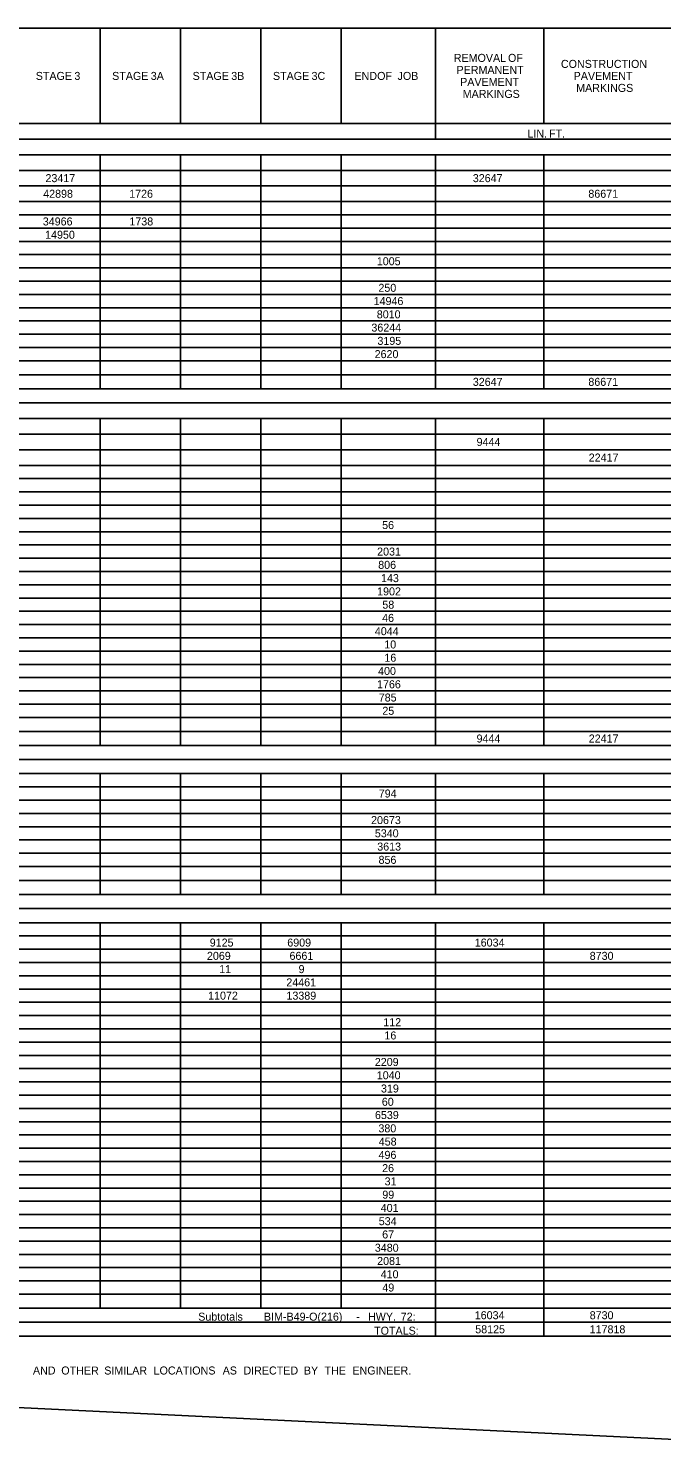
# Model space of a CAD drawing. Extents: x 1225909 to 1228704, y 151309 to 152305.
# Drawn here: x 1226949 to 1227206, y 151342 to 151915 of the extents above; entities that cross this region are included whole.
import ezdxf

# ---------------------------------------------------------------- set-up
doc = ezdxf.new("R2010")
doc.units = 0
doc.layers.add('R_Border', color=7, linetype='Continuous')
doc.layers.add('R_Dimension', color=7, linetype='Continuous')

msp = doc.modelspace()

# ---------------------------------------------------------------- linework, layer by layer
at = {"layer": 'R_Border'}
msp.add_lwpolyline([(1227672.06, 151397.84), (1227247.19, 151342), (1225968.58, 151404.15)], dxfattribs=at)
at = {"layer": 'R_Dimension'}
for p, q in [((1226577.42, 151914.54), (1228151.92, 151914.54)), ((1226978.35, 151876.02), (1226978.35, 151914.54)), ((1227010.86, 151876.02), (1227010.86, 151914.54)), ((1227043.38, 151876.02), (1227043.38, 151914.54)), ((1227075.89, 151876.02), (1227075.89, 151914.54)), ((1227114.09, 151869.71), (1227114.09, 151914.54)), ((1227157.97, 151876.02), (1227157.97, 151914.54)), ((1226750.73, 151876.02), (1228151.92, 151876.02)), ((1226577.42, 151869.71), (1228151.92, 151869.71)), ((1226577.42, 151863.4), (1228151.92, 151863.4)), ((1226978.35, 151768.69), (1226978.35, 151863.4)), ((1227010.86, 151768.69), (1227010.86, 151863.4)), ((1227043.38, 151768.69), (1227043.38, 151863.4)), ((1227075.89, 151768.69), (1227075.89, 151863.4)), ((1227114.09, 151768.69), (1227114.09, 151863.4)), ((1227157.97, 151768.69), (1227157.97, 151863.4)), ((1226577.42, 151857.08), (1228151.92, 151857.08)), ((1226577.42, 151850.77), (1228151.92, 151850.77)), ((1226577.42, 151844.45), (1228151.92, 151844.45)), ((1226577.42, 151839.09), (1228151.92, 151839.09)), ((1226577.42, 151833.72), (1228151.92, 151833.72)), ((1226577.42, 151828.35), (1228151.92, 151828.35)), ((1226577.42, 151822.99), (1228151.92, 151822.99)), ((1226577.42, 151817.62), (1228151.92, 151817.62)), ((1226577.42, 151812.25), (1228151.92, 151812.25)), ((1226577.42, 151806.89), (1228151.92, 151806.89)), ((1226577.42, 151801.52), (1228151.92, 151801.52)), ((1226577.42, 151796.15), (1228151.92, 151796.15)), ((1226577.42, 151790.79), (1228151.92, 151790.79)), ((1226577.42, 151785.42), (1228151.92, 151785.42)), ((1226577.42, 151780.05), (1228151.92, 151780.05)), ((1226577.42, 151774.37), (1228151.92, 151774.37)), ((1226577.42, 151768.69), (1228151.92, 151768.69)), ((1226577.42, 151763.01), (1228151.92, 151763.01)), ((1226577.42, 151756.69), (1228151.92, 151756.69)), ((1226978.35, 151624.42), (1226978.35, 151756.69)), ((1227010.86, 151624.42), (1227010.86, 151756.69)), ((1227043.38, 151624.42), (1227043.38, 151756.69)), ((1227075.89, 151624.42), (1227075.89, 151756.69)), ((1227114.09, 151624.42), (1227114.09, 151756.69)), ((1227157.97, 151624.42), (1227157.97, 151756.69)), ((1226577.42, 151750.38), (1228151.92, 151750.38)), ((1226577.42, 151744.07), (1228151.92, 151744.07)), ((1226577.42, 151737.75), (1228151.92, 151737.75)), ((1226577.42, 151732.39), (1228151.92, 151732.39)), ((1226577.42, 151727.02), (1228151.92, 151727.02)), ((1226577.42, 151721.65), (1228151.92, 151721.65)), ((1226577.42, 151716.29), (1228151.92, 151716.29)), ((1226577.42, 151710.92), (1228151.92, 151710.92)), ((1226577.42, 151705.55), (1228151.92, 151705.55)), ((1226577.42, 151700.18), (1228151.92, 151700.18)), ((1226577.42, 151694.82), (1228151.92, 151694.82)), ((1226577.42, 151689.45), (1228151.92, 151689.45)), ((1226577.42, 151684.08), (1228151.92, 151684.08)), ((1226577.42, 151678.72), (1228151.92, 151678.72)), ((1226577.42, 151673.35), (1228151.92, 151673.35)), ((1226577.42, 151667.98), (1228151.92, 151667.98)), ((1226577.42, 151662.62), (1228151.92, 151662.62)), ((1226577.42, 151657.25), (1228151.92, 151657.25)), ((1226577.42, 151651.88), (1228151.92, 151651.88)), ((1226577.42, 151646.52), (1228151.92, 151646.52)), ((1226577.42, 151641.15), (1228151.92, 151641.15)), ((1226577.42, 151635.78), (1228151.92, 151635.78)), ((1226577.42, 151630.1), (1228151.92, 151630.1)), ((1226577.42, 151624.42), (1228151.92, 151624.42)), ((1226577.42, 151618.74), (1228151.92, 151618.74)), ((1226577.42, 151613.05), (1228151.92, 151613.05)), ((1226978.35, 151564.12), (1226978.35, 151613.05)), ((1227010.86, 151564.12), (1227010.86, 151613.05)), ((1227043.38, 151564.12), (1227043.38, 151613.05)), ((1227075.89, 151564.12), (1227075.89, 151613.05)), ((1227114.09, 151564.12), (1227114.09, 151613.05)), ((1227157.97, 151564.12), (1227157.97, 151613.05)), ((1226577.42, 151607.69), (1228151.92, 151607.69)), ((1226577.42, 151602.32), (1228151.92, 151602.32)), ((1226577.42, 151596.95), (1228151.92, 151596.95)), ((1226577.42, 151591.59), (1228151.92, 151591.59)), ((1226577.42, 151586.22), (1228151.92, 151586.22)), ((1226577.42, 151580.85), (1228151.92, 151580.85)), ((1226577.42, 151575.49), (1228151.92, 151575.49)), ((1226577.42, 151569.81), (1228151.92, 151569.81)), ((1226577.42, 151564.12), (1228151.92, 151564.12)), ((1226577.42, 151558.44), (1228151.92, 151558.44)), ((1226577.42, 151552.76), (1228151.92, 151552.76)), ((1226978.35, 151396.81), (1226978.35, 151552.76)), ((1227010.86, 151396.81), (1227010.86, 151552.76)), ((1227043.38, 151396.81), (1227043.38, 151552.76)), ((1227075.89, 151396.81), (1227075.89, 151552.76)), ((1227114.09, 151385.44), (1227114.09, 151552.76)), ((1227157.97, 151385.44), (1227157.97, 151552.76)), ((1226577.42, 151547.39), (1228151.92, 151547.39)), ((1226577.42, 151542.02), (1228151.92, 151542.02)), ((1226577.42, 151536.66), (1228151.92, 151536.66)), ((1226577.42, 151531.29), (1228151.92, 151531.29)), ((1226577.42, 151525.92), (1228151.92, 151525.92)), ((1226577.42, 151520.56), (1228151.92, 151520.56)), ((1226577.42, 151515.19), (1228151.92, 151515.19)), ((1226577.42, 151509.82), (1228151.92, 151509.82)), ((1226577.42, 151504.46), (1228151.92, 151504.46)), ((1226577.42, 151499.09), (1228151.92, 151499.09)), ((1226577.42, 151493.72), (1228151.92, 151493.72)), ((1226577.42, 151488.36), (1228151.92, 151488.36)), ((1226577.42, 151482.99), (1228151.92, 151482.99)), ((1226577.42, 151477.62), (1228151.92, 151477.62)), ((1226577.42, 151472.26), (1228151.92, 151472.26)), ((1226577.42, 151466.89), (1228151.92, 151466.89)), ((1226577.42, 151461.52), (1228151.92, 151461.52)), ((1226577.42, 151456.16), (1228151.92, 151456.16)), ((1226577.42, 151450.79), (1228151.92, 151450.79)), ((1226577.42, 151445.42), (1228151.92, 151445.42)), ((1226577.42, 151440.06), (1228151.92, 151440.06)), ((1226577.42, 151434.69), (1228151.92, 151434.69)), ((1226577.42, 151429.32), (1228151.92, 151429.32)), ((1226577.42, 151423.96), (1228151.92, 151423.96)), ((1226577.42, 151418.59), (1228151.92, 151418.59)), ((1226577.42, 151413.22), (1228151.92, 151413.22)), ((1226577.42, 151407.86), (1228151.92, 151407.86)), ((1226577.42, 151402.49), (1228151.92, 151402.49)), ((1226577.42, 151396.81), (1228151.92, 151396.81)), ((1226577.42, 151391.13), (1228151.92, 151391.13)), ((1226577.42, 151385.44), (1228151.92, 151385.44))]:
    msp.add_line(p, q, dxfattribs=at)

# ---------------------------------------------------------------- texts
for s, height, p in [('REMOVAL', 3.238, (1227121.53, 151900.95)), ('PERMANENT', 3.238, (1227122.64, 151896.09)), (' OF', 3.238, (1227142.28, 151900.95)), ('CONSTRUCTION', 3.2378, (1227164.9, 151898.52)), ('STAGE', 3.238, (1226952.34, 151893.66)), (' 3', 3.238, (1226966.77, 151893.66)), ('STAGE', 3.238, (1226983.26, 151893.66)), (' 3A', 3.238, (1226997.69, 151893.66)), ('STAGE', 3.238, (1227015.83, 151893.66)), (' 3B', 3.238, (1227030.26, 151893.66)), ('STAGE', 3.238, (1227048.34, 151893.66)), (' 3C', 3.238, (1227062.77, 151893.66)), ('END', 3.238, (1227081.34, 151893.66)), (' OF', 3.238, (1227089.32, 151893.66)), (' JOB', 3.238, (1227097.58, 151893.66)), ('PAVEMENT', 3.238, (1227124.11, 151891.23)), ('PAVEMENT', 3.238, (1227170.05, 151893.66)), ('MARKINGS', 3.238, (1227125.15, 151886.38)), ('MARKINGS', 3.238, (1227171.08, 151888.81)), ('LIN.', 3.238, (1227151.34, 151870.36)), (' FT.', 3.238, (1227158.89, 151870.36)), ('23417', 3.238, (1226956.27, 151852.31)), ('32647', 3.238, (1227129.23, 151852.31)), ('42898', 3.238, (1226955.36, 151845.99)), ('1726', 3.238, (1226990.15, 151845.99)), ('86671', 3.238, (1227176, 151845.99)), ('34966', 3.238, (1226955.19, 151834.79)), ('1738', 3.238, (1226990.24, 151834.79)), ('14950', 3.238, (1226956.13, 151829.42)), ('1005', 3.238, (1227090.38, 151818.69)), ('250', 3.238, (1227091.03, 151807.95)), ('14946', 3.238, (1227089.09, 151802.59)), ('8010', 3.238, (1227090.37, 151797.22)), ('36244', 3.238, (1227088.19, 151791.85)), ('3195', 3.238, (1227090.63, 151786.49)), ('2620', 3.238, (1227089.5, 151781.12)), ('32647', 3.238, (1227129.23, 151769.91)), ('86671', 3.238, (1227176, 151769.91)), ('9444', 3.238, (1227130.76, 151745.6)), ('22417', 3.238, (1227176.15, 151739.29)), ('56', 3.238, (1227092.53, 151711.98)), ('2031', 3.238, (1227090.51, 151701.25)), ('806', 3.238, (1227090.95, 151695.88)), ('143', 3.238, (1227092.09, 151690.52)), ('1902', 3.238, (1227090.51, 151685.15)), ('58', 3.238, (1227092.62, 151679.78)), ('46', 3.238, (1227092.53, 151674.42)), ('4044', 3.238, (1227089.59, 151669.05)), ('10', 3.238, (1227093.4, 151663.68)), ('16', 3.238, (1227093.45, 151658.32)), ('400', 3.238, (1227090.9, 151652.95)), ('1766', 3.238, (1227090.47, 151647.58)), ('785', 3.238, (1227091.17, 151642.22)), ('25', 3.238, (1227092.62, 151636.85)), ('9444', 3.238, (1227130.76, 151625.64)), ('22417', 3.238, (1227176.15, 151625.64)), ('794', 3.238, (1227091.17, 151603.39)), ('20673', 3.238, (1227088.06, 151592.65)), ('5340', 3.238, (1227089.58, 151587.29)), ('3613', 3.238, (1227090.56, 151581.92)), ('856', 3.238, (1227091.08, 151576.55)), ('9125', 3.238, (1227022.76, 151543.09)), ('6909', 3.238, (1227054.14, 151543.09)), ('16034', 3.238, (1227130.02, 151543.09)), ('2069', 3.238, (1227021.63, 151537.72)), ('6661', 3.238, (1227055.05, 151537.72)), ('8730', 3.238, (1227176.55, 151537.72)), ('11', 3.238, (1227026.58, 151532.36)), ('9', 3.24, (1227058.71, 151532.36)), ('24461', 3.238, (1227053.75, 151526.99)), ('11072', 3.238, (1227022.1, 151521.62)), ('13389', 3.238, (1227053.81, 151521.62)), ('112', 3.238, (1227093, 151510.89)), ('16', 3.238, (1227093.45, 151505.52)), ('2209', 3.238, (1227089.58, 151494.79)), ('1040', 3.238, (1227090.37, 151489.42)), ('319', 3.238, (1227092.07, 151484.06)), ('60', 3.238, (1227092.41, 151478.69)), ('6539', 3.238, (1227089.63, 151473.32)), ('380', 3.238, (1227091.03, 151467.95)), ('458', 3.238, (1227091.17, 151462.59)), ('496', 3.238, (1227091.08, 151457.22)), ('26', 3.238, (1227092.53, 151451.85)), ('31', 3.238, (1227093.54, 151446.49)), ('99', 3.238, (1227092.61, 151441.12)), ('401', 3.238, (1227091.96, 151435.75)), ('534', 3.238, (1227091.17, 151430.39)), ('67', 3.238, (1227092.55, 151425.02)), ('3480', 3.238, (1227089.58, 151419.65)), ('2081', 3.238, (1227090.51, 151414.29)), ('410', 3.238, (1227091.95, 151408.92)), ('49', 3.238, (1227092.61, 151403.55)), ('16034', 3.238, (1227130.02, 151392.35)), ('8730', 3.238, (1227176.55, 151392.35)), ('Subtotals', 3.238, (1227018.11, 151391.77)), (' BIM-B49-O(216)', 3.2378, (1227043.5, 151391.77)), (' -', 3.238, (1227080.8, 151391.77)), (' HWY.', 3.238, (1227085.62, 151391.77)), (' 72:', 3.238, (1227098.85, 151391.77)), ('58125', 3.238, (1227130.22, 151386.66)), ('117818', 3.238, (1227176.53, 151386.66)), ('TOTALS:', 3.238, (1227089.29, 151386.09)), (' AND', 3.238, (1226950, 151369.99)), (' OTHER', 3.238, (1226961.47, 151369.99)), (' SIMILAR', 3.238, (1226978.86, 151369.99)), (' LOCATIONS', 3.238, (1226998.84, 151369.99)), (' AS', 3.238, (1227026.81, 151369.99)), (' DIRECTED', 3.238, (1227035.2, 151369.99)), (' BY', 3.238, (1227059.67, 151369.99)), (' THE', 3.238, (1227068.01, 151369.99)), (' ENGINEER.', 3.238, (1227079.3, 151369.99))]:
    msp.add_text(s, height=height, dxfattribs=at).set_placement(p)

doc.saveas('drawing.dxf')
